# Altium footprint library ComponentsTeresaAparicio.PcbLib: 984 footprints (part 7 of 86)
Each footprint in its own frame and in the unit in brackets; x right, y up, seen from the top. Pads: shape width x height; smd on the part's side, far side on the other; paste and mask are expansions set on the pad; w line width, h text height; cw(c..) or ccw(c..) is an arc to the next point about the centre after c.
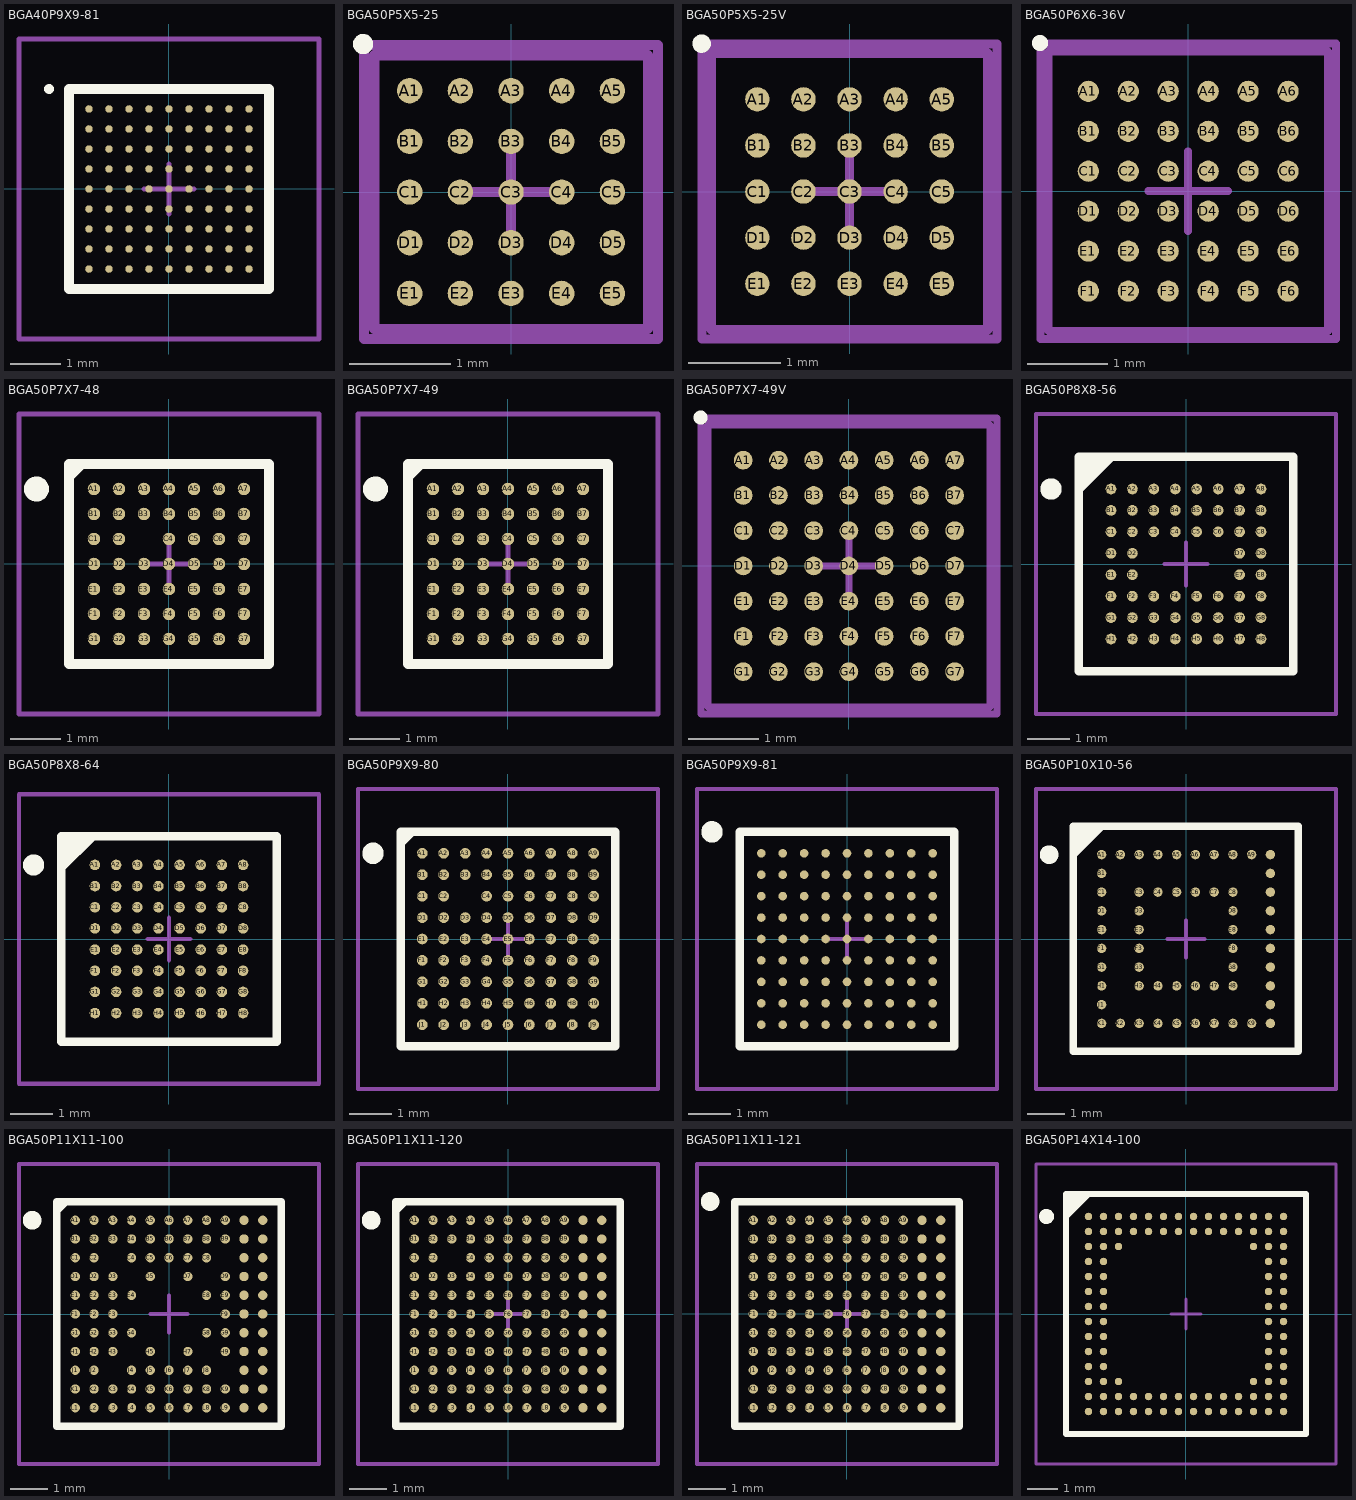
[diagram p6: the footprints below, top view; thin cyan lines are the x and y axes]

## BGA40P9X9-81 [mm] "BGA, 81-Leads, Body 4x4mm, Pitch 0.4mm"
height 0.8
pads (81):
  round 0.15 smd: A1(-1.6,1.6) A2(-1.2,1.6) A3(-0.8,1.6) A4(-0.4,1.6) A5(0,1.6) A6(0.4,1.6) A7(0.8,1.6) A8(1.2,1.6) A9(1.6,1.6) B1(-1.6,1.2) B2(-1.2,1.2) B3(-0.8,1.2) B4(-0.4,1.2) B5(0,1.2) B6(0.4,1.2) B7(0.8,1.2) B8(1.2,1.2) B9(1.6,1.2) C1(-1.6,0.8) C2(-1.2,0.8) C3(-0.8,0.8) C4(-0.4,0.8) C5(0,0.8) C6(0.4,0.8) C7(0.8,0.8) C8(1.2,0.8) C9(1.6,0.8) D1(-1.6,0.4) D2(-1.2,0.4) D3(-0.8,0.4) D4(-0.4,0.4) D5(0,0.4) D6(0.4,0.4) D7(0.8,0.4) D8(1.2,0.4) D9(1.6,0.4) E1(-1.6,0) E2(-1.2,0) E3(-0.8,0) E4(-0.4,0) E5(0,0) E6(0.4,0) E7(0.8,0) E8(1.2,0) E9(1.6,0) F1(-1.6,-0.4) F2(-1.2,-0.4) F3(-0.8,-0.4) F4(-0.4,-0.4) F5(0,-0.4) F6(0.4,-0.4) F7(0.8,-0.4) F8(1.2,-0.4) F9(1.6,-0.4) G1(-1.6,-0.8) G2(-1.2,-0.8) G3(-0.8,-0.8) G4(-0.4,-0.8) G5(0,-0.8) G6(0.4,-0.8) G7(0.8,-0.8) G8(1.2,-0.8) G9(1.6,-0.8) H1(-1.6,-1.2) H2(-1.2,-1.2) H3(-0.8,-1.2) H4(-0.4,-1.2) H5(0,-1.2) H6(0.4,-1.2) H7(0.8,-1.2) H8(1.2,-1.2) H9(1.6,-1.2) J1(-1.6,-1.6) J2(-1.2,-1.6) J3(-0.8,-1.6) J4(-0.4,-1.6) J5(0,-1.6) J6(0.4,-1.6) J7(0.8,-1.6) J8(1.2,-1.6) J9(1.6,-1.6)
Top Overlay:
  circle w0.1: c-2.4,2 r0.05
  lines w0.2: -2,-2 2,-2 2,2 -2,2 -2,-2
Mechanical 13:
  lines w0.1: -2,-2 2,-2 2,2 -2,2 -2,-2
Mechanical 15:
  lines w0.1: -0.5,0 0.5,0 ; 0,-0.5 0,0.5 ; -3,-3 3,-3 3,3 -3,3 -3,-3
3D body: height 0.8, standoff 0.05, extent -2,-2 2,2

## BGA50P5X5-25 [mm] "BGA, 25-Leads, Body 2.69x2.69mm, Pitch 0.5mm"
height 0.6
pads (25):
  round 0.25 smd: A1(-1,1) A2(-0.5,1) A3(0,1) A4(0.5,1) A5(1,1) B1(-1,0.5) B2(-0.5,0.5) B3(0,0.5) B4(0.5,0.5) B5(1,0.5) C1(-1,0) C2(-0.5,0) C3(0,0) C4(0.5,0) C5(1,0) D1(-1,-0.5) D2(-0.5,-0.5) D3(0,-0.5) D4(0.5,-0.5) D5(1,-0.5) E1(-1,-1) E2(-0.5,-1) E3(0,-1) E4(0.5,-1) E5(1,-1)
Top Overlay:
  circle w0.1: c-1.46,1.46 r0.05
Mechanical 13:
  lines w0.1: -1.35,-1.35 -1.35,1.35 1.35,1.35 1.35,-1.35 -1.35,-1.35
Mechanical 15:
  lines w0.1: -0.5,0 0.5,0 ; 0,-0.5 0,0.5 ; -1.45,-1.45 -1.45,1.45 1.45,1.45 1.45,-1.45 -1.45,-1.45
3D body: height 0.6, standoff 0.22, extent -1.35,-1.35 1.35,1.35

## BGA50P5X5-25V [mm] "BGA, 25-Leads, Body 3x3mm, Pitch 0.5mm, NSC Recommended"
height 1.1
pads (25):
  round 0.265 smd paste-0.132 mask+0.05: A1(-1,1) A2(-0.5,1) A3(0,1) A4(0.5,1) A5(1,1) B1(-1,0.5) B2(-0.5,0.5) B3(0,0.5) B4(0.5,0.5) B5(1,0.5) C1(-1,0) C2(-0.5,0) C3(0,0) C4(0.5,0) C5(1,0) D1(-1,-0.5) D2(-0.5,-0.5) D3(0,-0.5) D4(0.5,-0.5) D5(1,-0.5) E1(-1,-1) E2(-0.5,-1) E3(0,-1) E4(0.5,-1) E5(1,-1)
Top Overlay:
  circle w0.1: c-1.605,1.605 r0.05
Top Paste:
  drawing of 225 lines, arcs and shapes, not listed
Mechanical 13:
  lines w0.1: -1.5,-1.5 -1.5,1.5 1.5,1.5 1.5,-1.5 -1.5,-1.5
Mechanical 15:
  lines w0.1: -0.5,0 0.5,0 ; 0,-0.5 0,0.5 ; -1.6,-1.6 -1.6,1.6 1.6,1.6 1.6,-1.6 -1.6,-1.6
3D body: height 1.1, standoff 0, extent -1.5,-1.5 1.5,1.5

## BGA50P6X6-36V [mm] "BGA, 36-Leads, Body 3.5x3.5mm, Pitch 0.5mm, NSC Recommended"
height 1.1
pads (36):
  round 0.265 smd paste-0.132 mask+0.05: A1(-1.25,1.25) A2(-0.75,1.25) A3(-0.25,1.25) A4(0.25,1.25) A5(0.75,1.25) A6(1.25,1.25) B1(-1.25,0.75) B2(-0.75,0.75) B3(-0.25,0.75) B4(0.25,0.75) B5(0.75,0.75) B6(1.25,0.75) C1(-1.25,0.25) C2(-0.75,0.25) C3(-0.25,0.25) C4(0.25,0.25) C5(0.75,0.25) C6(1.25,0.25) D1(-1.25,-0.25) D2(-0.75,-0.25) D3(-0.25,-0.25) D4(0.25,-0.25) D5(0.75,-0.25) D6(1.25,-0.25) E1(-1.25,-0.75) E2(-0.75,-0.75) E3(-0.25,-0.75) E4(0.25,-0.75) E5(0.75,-0.75) E6(1.25,-0.75) F1(-1.25,-1.25) F2(-0.75,-1.25) F3(-0.25,-1.25) F4(0.25,-1.25) F5(0.75,-1.25) F6(1.25,-1.25)
Top Overlay:
  circle w0.1: c-1.855,1.855 r0.05
Top Paste:
  drawing of 324 lines, arcs and shapes, not listed
Mechanical 13:
  lines w0.1: -1.75,-1.75 -1.75,1.75 1.75,1.75 1.75,-1.75 -1.75,-1.75
Mechanical 15:
  lines w0.1: -0.5,0 0.5,0 ; 0,-0.5 0,0.5 ; -1.85,-1.85 -1.85,1.85 1.85,1.85 1.85,-1.85 -1.85,-1.85
3D body: height 1.1, standoff 0, extent -1.75,-1.75 1.75,1.75

## BGA50P7X7-48 [mm] "BGA, 48-Leads, Body 4x4mm, Pitch 0.5mm"
height 1
pads (48):
  round 0.25 smd: A1(-1.5,1.5) A2(-1,1.5) A3(-0.5,1.5) A4(0,1.5) A5(0.5,1.5) A6(1,1.5) A7(1.5,1.5) B1(-1.5,1) B2(-1,1) B3(-0.5,1) B4(0,1) B5(0.5,1) B6(1,1) B7(1.5,1) C1(-1.5,0.5) C2(-1,0.5) C4(0,0.5) C5(0.5,0.5) C6(1,0.5) C7(1.5,0.5) D1(-1.5,0) D2(-1,0) D3(-0.5,0) D4(0,0) D5(0.5,0) D6(1,0) D7(1.5,0) E1(-1.5,-0.5) E2(-1,-0.5) E3(-0.5,-0.5) E4(0,-0.5) E5(0.5,-0.5) E6(1,-0.5) E7(1.5,-0.5) F1(-1.5,-1) F2(-1,-1) F3(-0.5,-1) F4(0,-1) F5(0.5,-1) F6(1,-1) F7(1.5,-1) G1(-1.5,-1.5) G2(-1,-1.5) G3(-0.5,-1.5) G4(0,-1.5) G5(0.5,-1.5) G6(1,-1.5) G7(1.5,-1.5)
Top Overlay:
  circle w0.25: c-2.65,1.5 r0.125
  region: -1.742,2 -2,1.742 -2,2
  lines w0.2: -2,1.742 -1.742,2 ; -2,-2 2,-2 2,2 -2,2 -2,-2
Mechanical 13:
  lines w0.1: -2,-2 2,-2 2,2 -2,2 -2,-2
Mechanical 15:
  lines w0.1: -0.5,0 0.5,0 ; 0,-0.5 0,0.5 ; -3,-3 3,-3 3,3 -3,3 -3,-3
3D body: height 1, standoff 0, extent -2,-2 2,2

## BGA50P7X7-49 [mm] "BGA, 49-Leads, Body 4x4mm, Pitch 0.5mm"
height 1.1
pads (49):
  round 0.25 smd: A1(-1.5,1.5) A2(-1,1.5) A3(-0.5,1.5) A4(0,1.5) A5(0.5,1.5) A6(1,1.5) A7(1.5,1.5) B1(-1.5,1) B2(-1,1) B3(-0.5,1) B4(0,1) B5(0.5,1) B6(1,1) B7(1.5,1) C1(-1.5,0.5) C2(-1,0.5) C3(-0.5,0.5) C4(0,0.5) C5(0.5,0.5) C6(1,0.5) C7(1.5,0.5) D1(-1.5,0) D2(-1,0) D3(-0.5,0) D4(0,0) D5(0.5,0) D6(1,0) D7(1.5,0) E1(-1.5,-0.5) E2(-1,-0.5) E3(-0.5,-0.5) E4(0,-0.5) E5(0.5,-0.5) E6(1,-0.5) E7(1.5,-0.5) F1(-1.5,-1) F2(-1,-1) F3(-0.5,-1) F4(0,-1) F5(0.5,-1) F6(1,-1) F7(1.5,-1) G1(-1.5,-1.5) G2(-1,-1.5) G3(-0.5,-1.5) G4(0,-1.5) G5(0.5,-1.5) G6(1,-1.5) G7(1.5,-1.5)
Top Overlay:
  circle w0.25: c-2.65,1.5 r0.125
  region: -1.742,2 -2,1.742 -2,2
  lines w0.2: -2,1.742 -1.742,2 ; -2,-2 2,-2 2,2 -2,2 -2,-2
Mechanical 13:
  lines w0.1: -2,-2 2,-2 2,2 -2,2 -2,-2
Mechanical 15:
  lines w0.1: -0.5,0 0.5,0 ; 0,-0.5 0,0.5 ; -3,-3 3,-3 3,3 -3,3 -3,-3
3D body: height 1.1, standoff 0.18, extent -1.999,-1.999 1.999,1.999

## BGA50P7X7-49V [mm] "BGA, 49-Leads, Body 4x4mm, Pitch 0.5mm, NSC Recommended"
height 1.1
pads (49):
  round 0.265 smd paste-0.132 mask+0.05: A1(-1.5,1.5) A2(-1,1.5) A3(-0.5,1.5) A4(0,1.5) A5(0.5,1.5) A6(1,1.5) A7(1.5,1.5) B1(-1.5,1) B2(-1,1) B3(-0.5,1) B4(0,1) B5(0.5,1) B6(1,1) B7(1.5,1) C1(-1.5,0.5) C2(-1,0.5) C3(-0.5,0.5) C4(0,0.5) C5(0.5,0.5) C6(1,0.5) C7(1.5,0.5) D1(-1.5,0) D2(-1,0) D3(-0.5,0) D4(0,0) D5(0.5,0) D6(1,0) D7(1.5,0) E1(-1.5,-0.5) E2(-1,-0.5) E3(-0.5,-0.5) E4(0,-0.5) E5(0.5,-0.5) E6(1,-0.5) E7(1.5,-0.5) F1(-1.5,-1) F2(-1,-1) F3(-0.5,-1) F4(0,-1) F5(0.5,-1) F6(1,-1) F7(1.5,-1) G1(-1.5,-1.5) G2(-1,-1.5) G3(-0.5,-1.5) G4(0,-1.5) G5(0.5,-1.5) G6(1,-1.5) G7(1.5,-1.5)
Top Overlay:
  circle w0.1: c-2.105,2.105 r0.05
Top Paste:
  drawing of 441 lines, arcs and shapes, not listed
Mechanical 13:
  lines w0.1: -2,-2 2,-2 2,2 -2,2 -2,-2
Mechanical 15:
  lines w0.1: -0.5,0 0.5,0 ; 0,-0.5 0,0.5 ; -2.1,-2.1 2.1,-2.1 2.1,2.1 -2.1,2.1 -2.1,-2.1
3D body: height 1.1, standoff 0, extent -2,-2 2,2

## BGA50P8X8-56 [mm] "BGA, 56-Leads, Body 5x5mm, Pitch 0.5mm"
height 1
pads (56):
  round 0.25 smd: A1(-1.75,1.75) A2(-1.25,1.75) A3(-0.75,1.75) A4(-0.25,1.75) A5(0.25,1.75) A6(0.75,1.75) A7(1.25,1.75) A8(1.75,1.75) B1(-1.75,1.25) B2(-1.25,1.25) B3(-0.75,1.25) B4(-0.25,1.25) B5(0.25,1.25) B6(0.75,1.25) B7(1.25,1.25) B8(1.75,1.25) C1(-1.75,0.75) C2(-1.25,0.75) C3(-0.75,0.75) C4(-0.25,0.75) C5(0.25,0.75) C6(0.75,0.75) C7(1.25,0.75) C8(1.75,0.75) D1(-1.75,0.25) D2(-1.25,0.25) D7(1.25,0.25) D8(1.75,0.25) E1(-1.75,-0.25) E2(-1.25,-0.25) E7(1.25,-0.25) E8(1.75,-0.25) F1(-1.75,-0.75) F2(-1.25,-0.75) F3(-0.75,-0.75) F4(-0.25,-0.75) F5(0.25,-0.75) F6(0.75,-0.75) F7(1.25,-0.75) F8(1.75,-0.75) G1(-1.75,-1.25) G2(-1.25,-1.25) G3(-0.75,-1.25) G4(-0.25,-1.25) G5(0.25,-1.25) G6(0.75,-1.25) G7(1.25,-1.25) G8(1.75,-1.25) H1(-1.75,-1.75) H2(-1.25,-1.75) H3(-0.75,-1.75) H4(-0.25,-1.75) H5(0.25,-1.75) H6(0.75,-1.75) H7(1.25,-1.75) H8(1.75,-1.75)
Top Overlay:
  circle w0.25: c-3.15,1.75 r0.125
  region: -1.742,2.5 -2.5,1.742 -2.5,2.5
  lines w0.2: -2.5,1.742 -1.742,2.5 ; -2.5,-2.5 2.5,-2.5 2.5,2.5 -2.5,2.5 -2.5,-2.5
Mechanical 13:
  lines w0.1: -2.5,-2.5 2.5,-2.5 2.5,2.5 -2.5,2.5 -2.5,-2.5
Mechanical 15:
  lines w0.1: -0.5,0 0.5,0 ; 0,-0.5 0,0.5 ; -3.5,-3.5 3.5,-3.5 3.5,3.5 -3.5,3.5 -3.5,-3.5
3D body: height 1, standoff 0, extent -2.5,-2.5 2.5,2.5

## BGA50P8X8-64 [mm] "BGA, 64-Leads, Body 4.8x5.1mm, Pitch 0.5mm"
height 0.9
pads (64):
  round 0.25 smd: A1(-1.75,1.75) A2(-1.25,1.75) A3(-0.75,1.75) A4(-0.25,1.75) A5(0.25,1.75) A6(0.75,1.75) A7(1.25,1.75) A8(1.75,1.75) B1(-1.75,1.25) B2(-1.25,1.25) B3(-0.75,1.25) B4(-0.25,1.25) B5(0.25,1.25) B6(0.75,1.25) B7(1.25,1.25) B8(1.75,1.25) C1(-1.75,0.75) C2(-1.25,0.75) C3(-0.75,0.75) C4(-0.25,0.75) C5(0.25,0.75) C6(0.75,0.75) C7(1.25,0.75) C8(1.75,0.75) D1(-1.75,0.25) D2(-1.25,0.25) D3(-0.75,0.25) D4(-0.25,0.25) D5(0.25,0.25) D6(0.75,0.25) D7(1.25,0.25) D8(1.75,0.25) E1(-1.75,-0.25) E2(-1.25,-0.25) E3(-0.75,-0.25) E4(-0.25,-0.25) E5(0.25,-0.25) E6(0.75,-0.25) E7(1.25,-0.25) E8(1.75,-0.25) F1(-1.75,-0.75) F2(-1.25,-0.75) F3(-0.75,-0.75) F4(-0.25,-0.75) F5(0.25,-0.75) F6(0.75,-0.75) F7(1.25,-0.75) F8(1.75,-0.75) G1(-1.75,-1.25) G2(-1.25,-1.25) G3(-0.75,-1.25) G4(-0.25,-1.25) G5(0.25,-1.25) G6(0.75,-1.25) G7(1.25,-1.25) G8(1.75,-1.25) H1(-1.75,-1.75) H2(-1.25,-1.75) H3(-0.75,-1.75) H4(-0.25,-1.75) H5(0.25,-1.75) H6(0.75,-1.75) H7(1.25,-1.75) H8(1.75,-1.75)
Top Overlay:
  circle w0.25: c-3.2,1.75 r0.125
  region: -1.801,2.425 -2.55,1.676 -2.55,2.425
  lines w0.2: -2.55,1.676 -1.801,2.425 ; -2.55,-2.425 -2.55,2.425 2.55,2.425 2.55,-2.425 -2.55,-2.425
Mechanical 13:
  lines w0.1: -2.55,-2.425 -2.55,2.425 2.55,2.425 2.55,-2.425 -2.55,-2.425
Mechanical 15:
  lines w0.1: -0.5,0 0.5,0 ; 0,-0.5 0,0.5 ; -3.545,-3.42 -3.545,3.42 3.545,3.42 3.545,-3.42 -3.545,-3.42
3D body: height 0.9, standoff 0.25, extent -2.55,-2.425 2.55,2.425

## BGA50P9X9-80 [mm] "BGA, 80-Leads, Body 5x5mm, Pitch 0.5mm"
height 1
pads (80):
  round 0.25 smd: A1(-2,2) A2(-1.5,2) A3(-1,2) A4(-0.5,2) A5(0,2) A6(0.5,2) A7(1,2) A8(1.5,2) A9(2,2) B1(-2,1.5) B2(-1.5,1.5) B3(-1,1.5) B4(-0.5,1.5) B5(0,1.5) B6(0.5,1.5) B7(1,1.5) B8(1.5,1.5) B9(2,1.5) C1(-2,1) C2(-1.5,1) C4(-0.5,1) C5(0,1) C6(0.5,1) C7(1,1) C8(1.5,1) C9(2,1) D1(-2,0.5) D2(-1.5,0.5) D3(-1,0.5) D4(-0.5,0.5) D5(0,0.5) D6(0.5,0.5) D7(1,0.5) D8(1.5,0.5) D9(2,0.5) E1(-2,0) E2(-1.5,0) E3(-1,0) E4(-0.5,0) E5(0,0) E6(0.5,0) E7(1,0) E8(1.5,0) E9(2,0) F1(-2,-0.5) F2(-1.5,-0.5) F3(-1,-0.5) F4(-0.5,-0.5) F5(0,-0.5) F6(0.5,-0.5) F7(1,-0.5) F8(1.5,-0.5) F9(2,-0.5) G1(-2,-1) G2(-1.5,-1) G3(-1,-1) G4(-0.5,-1) G5(0,-1) G6(0.5,-1) G7(1,-1) G8(1.5,-1) G9(2,-1) H1(-2,-1.5) H2(-1.5,-1.5) H3(-1,-1.5) H4(-0.5,-1.5) H5(0,-1.5) H6(0.5,-1.5) H7(1,-1.5) H8(1.5,-1.5) H9(2,-1.5) J1(-2,-2) J2(-1.5,-2) J3(-1,-2) J4(-0.5,-2) J5(0,-2) J6(0.5,-2) J7(1,-2) J8(1.5,-2) J9(2,-2)
Top Overlay:
  circle w0.25: c-3.15,2 r0.125
  region: -2.242,2.5 -2.5,2.242 -2.5,2.5
  lines w0.2: -2.5,2.242 -2.242,2.5 ; -2.5,-2.5 -2.5,2.5 2.5,2.5 2.5,-2.5 -2.5,-2.5
Mechanical 13:
  lines w0.1: -2.5,-2.5 -2.5,2.5 2.5,2.5 2.5,-2.5 -2.5,-2.5
Mechanical 15:
  lines w0.1: -0.5,0 0.5,0 ; 0,-0.5 0,0.5 ; -3.5,-3.5 -3.5,3.5 3.5,3.5 3.5,-3.5 -3.5,-3.5
3D body: height 1, standoff 0, extent -2.5,-2.5 2.5,2.5

## BGA50P9X9-81 [mm] "BGA, 81-Leads, Body 5x5mm, Pitch 0.5mm"
height 0.8
pads (81):
  round 0.2 smd: A1(-2,2) A2(-1.5,2) A3(-1,2) A4(-0.5,2) A5(0,2) A6(0.5,2) A7(1,2) A8(1.5,2) A9(2,2) B1(-2,1.5) B2(-1.5,1.5) B3(-1,1.5) B4(-0.5,1.5) B5(0,1.5) B6(0.5,1.5) B7(1,1.5) B8(1.5,1.5) B9(2,1.5) C1(-2,1) C2(-1.5,1) C3(-1,1) C4(-0.5,1) C5(0,1) C6(0.5,1) C7(1,1) C8(1.5,1) C9(2,1) D1(-2,0.5) D2(-1.5,0.5) D3(-1,0.5) D4(-0.5,0.5) D5(0,0.5) D6(0.5,0.5) D7(1,0.5) D8(1.5,0.5) D9(2,0.5) E1(-2,0) E2(-1.5,0) E3(-1,0) E4(-0.5,0) E5(0,0) E6(0.5,0) E7(1,0) E8(1.5,0) E9(2,0) F1(-2,-0.5) F2(-1.5,-0.5) F3(-1,-0.5) F4(-0.5,-0.5) F5(0,-0.5) F6(0.5,-0.5) F7(1,-0.5) F8(1.5,-0.5) F9(2,-0.5) G1(-2,-1) G2(-1.5,-1) G3(-1,-1) G4(-0.5,-1) G5(0,-1) G6(0.5,-1) G7(1,-1) G8(1.5,-1) G9(2,-1) H1(-2,-1.5) H2(-1.5,-1.5) H3(-1,-1.5) H4(-0.5,-1.5) H5(0,-1.5) H6(0.5,-1.5) H7(1,-1.5) H8(1.5,-1.5) H9(2,-1.5) J1(-2,-2) J2(-1.5,-2) J3(-1,-2) J4(-0.5,-2) J5(0,-2) J6(0.5,-2) J7(1,-2) J8(1.5,-2) J9(2,-2)
Top Overlay:
  circle w0.25: c-3.15,2.5 r0.125
  lines w0.2: -2.5,-2.5 2.5,-2.5 2.5,2.5 -2.5,2.5 -2.5,-2.5
Mechanical 13:
  lines w0.1: -2.5,-2.5 2.5,-2.5 2.5,2.5 -2.5,2.5 -2.5,-2.5
Mechanical 15:
  lines w0.1: -0.5,0 0.5,0 ; 0,-0.5 0,0.5 ; -3.5,-3.5 3.5,-3.5 3.5,3.5 -3.5,3.5 -3.5,-3.5
3D body: height 0.8, standoff 0.05, extent -2.5,-2.5 2.5,2.5

## BGA50P10X10-56 [mm] "BGA, 56-Leads, Body 6x6mm, Pitch 0.5mm"
height 1.35
pads (56):
  round 0.25 smd: A1(-2.25,2.25) A2(-1.75,2.25) A3(-1.25,2.25) A4(-0.75,2.25) A5(-0.25,2.25) A6(0.25,2.25) A7(0.75,2.25) A8(1.25,2.25) A9(1.75,2.25) A10(2.25,2.25) B1(-2.25,1.75) B10(2.25,1.75) C1(-2.25,1.25) C3(-1.25,1.25) C4(-0.75,1.25) C5(-0.25,1.25) C6(0.25,1.25) C7(0.75,1.25) C8(1.25,1.25) C10(2.25,1.25) D1(-2.25,0.75) D3(-1.25,0.75) D8(1.25,0.75) D10(2.25,0.75) E1(-2.25,0.25) E3(-1.25,0.25) E8(1.25,0.25) E10(2.25,0.25) F1(-2.25,-0.25) F3(-1.25,-0.25) F8(1.25,-0.25) F10(2.25,-0.25) G1(-2.25,-0.75) G3(-1.25,-0.75) G8(1.25,-0.75) G10(2.25,-0.75) H1(-2.25,-1.25) H3(-1.25,-1.25) H4(-0.75,-1.25) H5(-0.25,-1.25) H6(0.25,-1.25) H7(0.75,-1.25) H8(1.25,-1.25) H10(2.25,-1.25) J1(-2.25,-1.75) J10(2.25,-1.75) K1(-2.25,-2.25) K2(-1.75,-2.25) K3(-1.25,-2.25) K4(-0.75,-2.25) K5(-0.25,-2.25) K6(0.25,-2.25) K7(0.75,-2.25) K8(1.25,-2.25) K9(1.75,-2.25) K10(2.25,-2.25)
Top Overlay:
  circle w0.25: c-3.65,2.25 r0.125
  region: -2.242,3 -3,2.242 -3,3
  lines w0.2: -3,2.242 -2.242,3 ; -3,-3 3,-3 3,3 -3,3 -3,-3
Mechanical 13:
  lines w0.1: -3,-3 3,-3 3,3 -3,3 -3,-3
Mechanical 15:
  lines w0.1: -0.5,0 0.5,0 ; 0,-0.5 0,0.5 ; -4,-4 4,-4 4,4 -4,4 -4,-4
3D body: height 1.35, standoff 0, extent -3,-3 3,3

## BGA50P11X11-100 [mm] "BGA, 100-Leads, Body 6x6mm, Pitch 0.5mm"
height 1.2
pads (100):
  round 0.25 smd: A1(-2.5,2.5) A2(-2,2.5) A3(-1.5,2.5) A4(-1,2.5) A5(-0.5,2.5) A6(0,2.5) A7(0.5,2.5) A8(1,2.5) A9(1.5,2.5) A10(2,2.5) A11(2.5,2.5) B1(-2.5,2) B2(-2,2) B3(-1.5,2) B4(-1,2) B5(-0.5,2) B6(0,2) B7(0.5,2) B8(1,2) B9(1.5,2) B10(2,2) B11(2.5,2) C1(-2.5,1.5) C2(-2,1.5) C4(-1,1.5) C5(-0.5,1.5) C6(0,1.5) C7(0.5,1.5) C8(1,1.5) C10(2,1.5) C11(2.5,1.5) D1(-2.5,1) D2(-2,1) D3(-1.5,1) D5(-0.5,1) D7(0.5,1) D9(1.5,1) D10(2,1) D11(2.5,1) E1(-2.5,0.5) E2(-2,0.5) E3(-1.5,0.5) E4(-1,0.5) E8(1,0.5) E9(1.5,0.5) E10(2,0.5) E11(2.5,0.5) F1(-2.5,0) F2(-2,0) F3(-1.5,0) F9(1.5,0) F10(2,0) F11(2.5,0) G1(-2.5,-0.5) G2(-2,-0.5) G3(-1.5,-0.5) G4(-1,-0.5) G8(1,-0.5) G9(1.5,-0.5) G10(2,-0.5) G11(2.5,-0.5) H1(-2.5,-1) H2(-2,-1) H3(-1.5,-1) H5(-0.5,-1) H7(0.5,-1) H9(1.5,-1) H10(2,-1) H11(2.5,-1) J1(-2.5,-1.5) J2(-2,-1.5) J4(-1,-1.5) J5(-0.5,-1.5) J6(0,-1.5) J7(0.5,-1.5) J8(1,-1.5) J10(2,-1.5) J11(2.5,-1.5) K1(-2.5,-2) K2(-2,-2) K3(-1.5,-2) K4(-1,-2) K5(-0.5,-2) K6(0,-2) K7(0.5,-2) K8(1,-2) K9(1.5,-2) K10(2,-2) K11(2.5,-2) L1(-2.5,-2.5) L2(-2,-2.5) L3(-1.5,-2.5) L4(-1,-2.5) L5(-0.5,-2.5) L6(0,-2.5) L7(0.5,-2.5) L8(1,-2.5) L9(1.5,-2.5) L10(2,-2.5) L11(2.5,-2.5)
Top Overlay:
  circle w0.25: c-3.65,2.5 r0.125
  region: -2.742,3 -3,2.742 -3,3
  lines w0.2: -3,2.742 -2.742,3 ; -3,-3 3,-3 3,3 -3,3 -3,-3
Mechanical 13:
  lines w0.1: -3,-3 3,-3 3,3 -3,3 -3,-3
Mechanical 15:
  lines w0.1: -0.5,0 0.5,0 ; 0,-0.5 0,0.5 ; -4,-4 4,-4 4,4 -4,4 -4,-4
3D body: height 1, standoff 0, extent -3,-3 3,3

## BGA50P11X11-120 [mm] "BGA, 120-Leads, Body 6x6mm, Pitch 0.5mm"
height 1
pads (120):
  round 0.25 smd: A1(-2.5,2.5) A2(-2,2.5) A3(-1.5,2.5) A4(-1,2.5) A5(-0.5,2.5) A6(0,2.5) A7(0.5,2.5) A8(1,2.5) A9(1.5,2.5) A10(2,2.5) A11(2.5,2.5) B1(-2.5,2) B2(-2,2) B3(-1.5,2) B4(-1,2) B5(-0.5,2) B6(0,2) B7(0.5,2) B8(1,2) B9(1.5,2) B10(2,2) B11(2.5,2) C1(-2.5,1.5) C2(-2,1.5) C4(-1,1.5) C5(-0.5,1.5) C6(0,1.5) C7(0.5,1.5) C8(1,1.5) C9(1.5,1.5) C10(2,1.5) C11(2.5,1.5) D1(-2.5,1) D2(-2,1) D3(-1.5,1) D4(-1,1) D5(-0.5,1) D6(0,1) D7(0.5,1) D8(1,1) D9(1.5,1) D10(2,1) D11(2.5,1) E1(-2.5,0.5) E2(-2,0.5) E3(-1.5,0.5) E4(-1,0.5) E5(-0.5,0.5) E6(0,0.5) E7(0.5,0.5) E8(1,0.5) E9(1.5,0.5) E10(2,0.5) E11(2.5,0.5) F1(-2.5,0) F2(-2,0) F3(-1.5,0) F4(-1,0) F5(-0.5,0) F6(0,0) F7(0.5,0) F8(1,0) F9(1.5,0) F10(2,0) F11(2.5,0) G1(-2.5,-0.5) G2(-2,-0.5) G3(-1.5,-0.5) G4(-1,-0.5) G5(-0.5,-0.5) G6(0,-0.5) G7(0.5,-0.5) G8(1,-0.5) G9(1.5,-0.5) G10(2,-0.5) G11(2.5,-0.5) H1(-2.5,-1) H2(-2,-1) H3(-1.5,-1) H4(-1,-1) H5(-0.5,-1) H6(0,-1) H7(0.5,-1) H8(1,-1) H9(1.5,-1) H10(2,-1) H11(2.5,-1) J1(-2.5,-1.5) J2(-2,-1.5) J3(-1.5,-1.5) J4(-1,-1.5) J5(-0.5,-1.5) J6(0,-1.5) J7(0.5,-1.5) J8(1,-1.5) J9(1.5,-1.5) J10(2,-1.5) J11(2.5,-1.5) K1(-2.5,-2) K2(-2,-2) K3(-1.5,-2) K4(-1,-2) K5(-0.5,-2) K6(0,-2) K7(0.5,-2) K8(1,-2) K9(1.5,-2) K10(2,-2) K11(2.5,-2) L1(-2.5,-2.5) L2(-2,-2.5) L3(-1.5,-2.5) L4(-1,-2.5) L5(-0.5,-2.5) L6(0,-2.5) L7(0.5,-2.5) L8(1,-2.5) L9(1.5,-2.5) L10(2,-2.5) L11(2.5,-2.5)
Top Overlay:
  circle w0.25: c-3.65,2.5 r0.125
  region: -2.742,3 -3,2.742 -3,3
  lines w0.2: -3,2.742 -2.742,3 ; -3,-3 -3,3 3,3 3,-3 -3,-3
Mechanical 13:
  lines w0.1: -3,-3 -3,3 3,3 3,-3 -3,-3
Mechanical 15:
  lines w0.1: -0.5,0 0.5,0 ; 0,-0.5 0,0.5 ; -4,-4 -4,4 4,4 4,-4 -4,-4
3D body: height 1, standoff 0, extent -3,-3 3,3

## BGA50P11X11-121 [mm] "BGA, 121-Leads, Body 6x6mm, Pitch 0.5mm"
height 0.99
pads (121):
  round 0.25 smd: A1(-2.5,2.5) A2(-2,2.5) A3(-1.5,2.5) A4(-1,2.5) A5(-0.5,2.5) A6(0,2.5) A7(0.5,2.5) A8(1,2.5) A9(1.5,2.5) A10(2,2.5) A11(2.5,2.5) B1(-2.5,2) B2(-2,2) B3(-1.5,2) B4(-1,2) B5(-0.5,2) B6(0,2) B7(0.5,2) B8(1,2) B9(1.5,2) B10(2,2) B11(2.5,2) C1(-2.5,1.5) C2(-2,1.5) C3(-1.5,1.5) C4(-1,1.5) C5(-0.5,1.5) C6(0,1.5) C7(0.5,1.5) C8(1,1.5) C9(1.5,1.5) C10(2,1.5) C11(2.5,1.5) D1(-2.5,1) D2(-2,1) D3(-1.5,1) D4(-1,1) D5(-0.5,1) D6(0,1) D7(0.5,1) D8(1,1) D9(1.5,1) D10(2,1) D11(2.5,1) E1(-2.5,0.5) E2(-2,0.5) E3(-1.5,0.5) E4(-1,0.5) E5(-0.5,0.5) E6(0,0.5) E7(0.5,0.5) E8(1,0.5) E9(1.5,0.5) E10(2,0.5) E11(2.5,0.5) F1(-2.5,0) F2(-2,0) F3(-1.5,0) F4(-1,0) F5(-0.5,0) F6(0,0) F7(0.5,0) F8(1,0) F9(1.5,0) F10(2,0) F11(2.5,0) G1(-2.5,-0.5) G2(-2,-0.5) G3(-1.5,-0.5) G4(-1,-0.5) G5(-0.5,-0.5) G6(0,-0.5) G7(0.5,-0.5) G8(1,-0.5) G9(1.5,-0.5) G10(2,-0.5) G11(2.5,-0.5) H1(-2.5,-1) H2(-2,-1) H3(-1.5,-1) H4(-1,-1) H5(-0.5,-1) H6(0,-1) H7(0.5,-1) H8(1,-1) H9(1.5,-1) H10(2,-1) H11(2.5,-1) J1(-2.5,-1.5) J2(-2,-1.5) J3(-1.5,-1.5) J4(-1,-1.5) J5(-0.5,-1.5) J6(0,-1.5) J7(0.5,-1.5) J8(1,-1.5) J9(1.5,-1.5) J10(2,-1.5) J11(2.5,-1.5) K1(-2.5,-2) K2(-2,-2) K3(-1.5,-2) K4(-1,-2) K5(-0.5,-2) K6(0,-2) K7(0.5,-2) K8(1,-2) K9(1.5,-2) K10(2,-2) K11(2.5,-2) L1(-2.5,-2.5) L2(-2,-2.5) L3(-1.5,-2.5) L4(-1,-2.5) L5(-0.5,-2.5) L6(0,-2.5) L7(0.5,-2.5) L8(1,-2.5) L9(1.5,-2.5) L10(2,-2.5) L11(2.5,-2.5)
Top Overlay:
  circle w0.25: c-3.65,3 r0.125
  lines w0.2: -3,-3 -3,3 3,3 3,-3 -3,-3
Mechanical 13:
  lines w0.1: -3,-3 -3,3 3,3 3,-3 -3,-3
Mechanical 15:
  lines w0.1: -0.5,0 0.5,0 ; 0,-0.5 0,0.5 ; -4,-4 -4,4 4,4 4,-4 -4,-4
3D body: height 0.99, standoff 0.18, extent -3,-3 3,3

## BGA50P14X14-100 [mm] "BGA, 100-Leads, Body 8x8mm, Pitch 0.5mm"
height 1.35
pads (100):
  round 0.25 smd: A1(-3.25,3.25) A2(-2.75,3.25) A3(-2.25,3.25) A4(-1.75,3.25) A5(-1.25,3.25) A6(-0.75,3.25) A7(-0.25,3.25) A8(0.25,3.25) A9(0.75,3.25) A10(1.25,3.25) A11(1.75,3.25) A12(2.25,3.25) A13(2.75,3.25) A14(3.25,3.25) B1(-3.25,2.75) B2(-2.75,2.75) B3(-2.25,2.75) B4(-1.75,2.75) B5(-1.25,2.75) B6(-0.75,2.75) B7(-0.25,2.75) B8(0.25,2.75) B9(0.75,2.75) B10(1.25,2.75) B11(1.75,2.75) B12(2.25,2.75) B13(2.75,2.75) B14(3.25,2.75) C1(-3.25,2.25) C2(-2.75,2.25) C3(-2.25,2.25) C12(2.25,2.25) C13(2.75,2.25) C14(3.25,2.25) D1(-3.25,1.75) D2(-2.75,1.75) D13(2.75,1.75) D14(3.25,1.75) E1(-3.25,1.25) E2(-2.75,1.25) E13(2.75,1.25) E14(3.25,1.25) F1(-3.25,0.75) F2(-2.75,0.75) F13(2.75,0.75) F14(3.25,0.75) G1(-3.25,0.25) G2(-2.75,0.25) G13(2.75,0.25) G14(3.25,0.25) H1(-3.25,-0.25) H2(-2.75,-0.25) H13(2.75,-0.25) H14(3.25,-0.25) J1(-3.25,-0.75) J2(-2.75,-0.75) J13(2.75,-0.75) J14(3.25,-0.75) K1(-3.25,-1.25) K2(-2.75,-1.25) K13(2.75,-1.25) K14(3.25,-1.25) L1(-3.25,-1.75) L2(-2.75,-1.75) L13(2.75,-1.75) L14(3.25,-1.75) M1(-3.25,-2.25) M2(-2.75,-2.25) M3(-2.25,-2.25) M12(2.25,-2.25) M13(2.75,-2.25) M14(3.25,-2.25) N1(-3.25,-2.75) N2(-2.75,-2.75) N3(-2.25,-2.75) N4(-1.75,-2.75) N5(-1.25,-2.75) N6(-0.75,-2.75) N7(-0.25,-2.75) N8(0.25,-2.75) N9(0.75,-2.75) N10(1.25,-2.75) N11(1.75,-2.75) N12(2.25,-2.75) N13(2.75,-2.75) N14(3.25,-2.75) P1(-3.25,-3.25) P2(-2.75,-3.25) P3(-2.25,-3.25) P4(-1.75,-3.25) P5(-1.25,-3.25) P6(-0.75,-3.25) P7(-0.25,-3.25) P8(0.25,-3.25) P9(0.75,-3.25) P10(1.25,-3.25) P11(1.75,-3.25) P12(2.25,-3.25) P13(2.75,-3.25) P14(3.25,-3.25)
Top Overlay:
  circle w0.25: c-4.65,3.25 r0.125
  region: -3.242,4 -4,3.242 -4,4
  lines w0.2: -4,3.242 -3.242,4 ; -4,-4 4,-4 4,4 -4,4 -4,-4
Mechanical 13:
  lines w0.1: -4,-4 4,-4 4,4 -4,4 -4,-4
Mechanical 15:
  lines w0.1: -0.5,0 0.5,0 ; 0,-0.5 0,0.5 ; -5,-5 5,-5 5,5 -5,5 -5,-5
3D body: height 1.35, standoff 0, extent -4,-4 4,4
